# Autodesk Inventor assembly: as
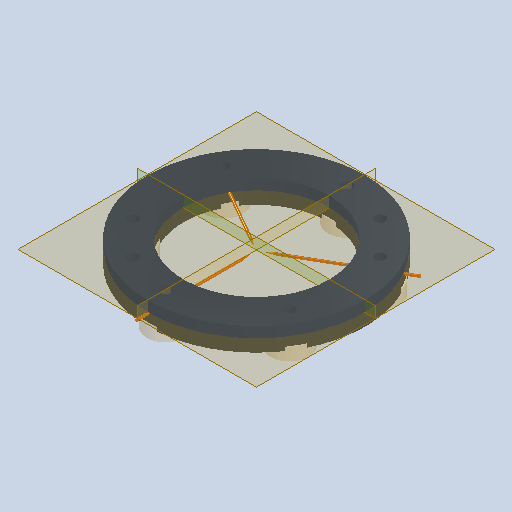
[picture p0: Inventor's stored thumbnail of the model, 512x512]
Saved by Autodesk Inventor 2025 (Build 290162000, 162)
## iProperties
Created: 2025-01
Part Number: as
Document SubType Name: Assembly
Designer: dansp
Author: dansp
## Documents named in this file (5)
- C:\Users\dansp\Desktop\DP\Model\as.iam
- C:\Users\dansp\Desktop\DP\Model\t1.ipt
- C:\Users\dansp\Desktop\DP\Model\t3.ipt
- C:\Users\dansp\Desktop\DP\Model\needle.ipt
- C:\Users\dansp\Desktop\DP\Model\t2.ipt
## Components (11 placed, 4 different names)
1. t1:1 — Mate:1, Flush:1, Mate:2, Flush:2, Mate:3, Tangent:1, Tangent:2, Mate:4, Mate:5
2. t2:1 — Mate:4, Mate:5, Mate:6
3. t3:1 — Flush:2, Mate:3
4. t3:2
5. t3:3
6. t3:4
7. t3:5
8. t3:6
9. needle:1 — Tangent:1, Tangent:2
10. needle:2
11. needle:3
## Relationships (10: Mate 6, Flush 2, Tangent 2)
- Mate:1: t1:1
- Flush:1: t1:1
- Mate:2: t1:1
- Flush:2: t1:1 ↔ t3:1
- Mate:3: t1:1 ↔ t3:1
- Tangent:1: t1:1 ↔ needle:1
- Tangent:2: t1:1 ↔ needle:1
- Mate:4: t1:1 ↔ t2:1
- Mate:5: t1:1 ↔ t2:1
- Mate:6: t2:1
